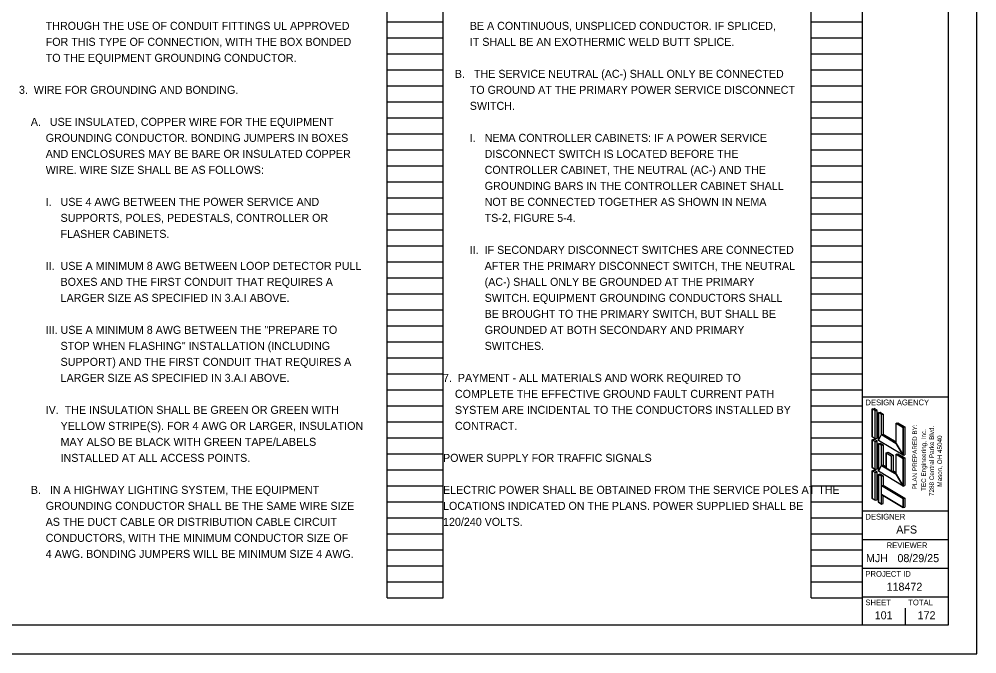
# Model space of a CAD drawing. Extents: x 0 to 34, y 0 to 22.
# Drawn here: x 17.24 to 34, y 0 to 11.11 of the extents above; entities that cross this region are included whole.
import ezdxf

# ---------------------------------------------------------------- set-up
doc = ezdxf.new("R2010")
doc.units = 0
for name, color, linetype in [('Default', 7, 'Continuous'), ('SH_Border', 7, 'Continuous'), ('SH_Cut_Line', 7, 'Continuous'), ('SH_Data', 7, 'Continuous'), ('SH_Text', 7, 'Continuous')]:
    doc.layers.add(name, color=color, linetype=linetype)

msp = doc.modelspace()

# ---------------------------------------------------------------- linework, layer by layer
at = {"layer": 'SH_Border'}
for p, q in [((32, 0.5), (32, 21.5)), ((32, 4.5), (33.5, 4.5)), ((32, 2.5), (33.5, 2.5)), ((32, 2), (33.5, 2)), ((32, 1.5), (33.5, 1.5)), ((32, 1), (33.5, 1))]:
    msp.add_line(p, q, dxfattribs=at)
msp.add_lwpolyline([(1.5, 21.5), (33.5, 21.5), (33.5, 0.5), (1.5, 0.5)], close=True, dxfattribs=at)
at = {"layer": 'SH_Cut_Line'}
msp.add_lwpolyline([(0, 0), (34, 0), (34, 22), (0, 22)], close=True, dxfattribs=at)
at = {"layer": 'SH_Data'}
for p, q in [((23.68, 0.98), (23.68, 21.14)), ((24.66, 0.98), (24.66, 21.14)), ((31.1, 0.98), (31.1, 21.14)), ((32, 0.98), (32, 21.14)), ((23.68, 11.06), (24.66, 11.06)), ((31.1, 11.06), (32, 11.06)), ((23.68, 10.78), (24.66, 10.78)), ((31.1, 10.78), (32, 10.78)), ((23.68, 10.5), (24.66, 10.5)), ((31.1, 10.5), (32, 10.5)), ((23.68, 10.22), (24.66, 10.22)), ((31.1, 10.22), (32, 10.22)), ((23.68, 9.94), (24.66, 9.94)), ((31.1, 9.94), (32, 9.94)), ((23.68, 9.66), (24.66, 9.66)), ((31.1, 9.66), (32, 9.66)), ((23.68, 9.38), (24.66, 9.38)), ((31.1, 9.38), (32, 9.38)), ((23.68, 9.1), (24.66, 9.1)), ((31.1, 9.1), (32, 9.1)), ((23.68, 8.82), (24.66, 8.82)), ((31.1, 8.82), (32, 8.82)), ((23.68, 8.54), (24.66, 8.54)), ((31.1, 8.54), (32, 8.54)), ((23.68, 8.26), (24.66, 8.26)), ((31.1, 8.26), (32, 8.26)), ((23.68, 7.98), (24.66, 7.98)), ((31.1, 7.98), (32, 7.98)), ((23.68, 7.7), (24.66, 7.7)), ((31.1, 7.7), (32, 7.7)), ((23.68, 7.42), (24.66, 7.42)), ((31.1, 7.42), (32, 7.42)), ((23.68, 7.14), (24.66, 7.14)), ((31.1, 7.14), (32, 7.14)), ((23.68, 6.86), (24.66, 6.86)), ((31.1, 6.86), (32, 6.86)), ((23.68, 6.58), (24.66, 6.58)), ((31.1, 6.58), (32, 6.58)), ((23.68, 6.3), (24.66, 6.3)), ((31.1, 6.3), (32, 6.3)), ((23.68, 6.02), (24.66, 6.02)), ((31.1, 6.02), (32, 6.02)), ((23.68, 5.74), (24.66, 5.74)), ((31.1, 5.74), (32, 5.74)), ((23.68, 5.46), (24.66, 5.46)), ((31.1, 5.46), (32, 5.46)), ((23.68, 5.18), (24.66, 5.18)), ((31.1, 5.18), (32, 5.18)), ((23.68, 4.9), (24.66, 4.9)), ((31.1, 4.9), (32, 4.9)), ((23.68, 4.62), (24.66, 4.62)), ((31.1, 4.62), (32, 4.62)), ((23.68, 4.34), (24.66, 4.34)), ((31.1, 4.34), (32, 4.34)), ((23.68, 4.06), (24.66, 4.06)), ((31.1, 4.06), (32, 4.06)), ((23.68, 3.78), (24.66, 3.78)), ((31.1, 3.78), (32, 3.78)), ((23.68, 3.5), (24.66, 3.5)), ((31.1, 3.5), (32, 3.5)), ((32.75, 3.5), (32.75, 3.5)), ((23.68, 3.22), (24.66, 3.22)), ((31.1, 3.22), (32, 3.22)), ((23.68, 2.94), (24.66, 2.94)), ((31.1, 2.94), (32, 2.94)), ((23.68, 2.66), (24.66, 2.66)), ((31.1, 2.66), (32, 2.66)), ((23.68, 2.38), (24.66, 2.38)), ((31.1, 2.38), (32, 2.38)), ((23.68, 2.1), (24.66, 2.1)), ((31.1, 2.1), (32, 2.1)), ((23.68, 1.82), (24.66, 1.82)), ((31.1, 1.82), (32, 1.82)), ((23.68, 1.54), (24.66, 1.54)), ((31.1, 1.54), (32, 1.54)), ((23.68, 1.26), (24.66, 1.26)), ((31.1, 1.26), (32, 1.26)), ((23.68, 0.98), (24.66, 0.98)), ((31.1, 0.98), (32, 0.98)), ((32.375, 0.675), (32.375, 0.675)), ((32.75, 0.5), (32.75, 0.8))]:
    msp.add_line(p, q, dxfattribs=at)
at = {"layer": 'SH_Text'}
for p, q in [((32.169, 4.285), (32.201, 4.294)), ((32.169, 3.799), (32.169, 4.285)), ((32.223, 4.253), (32.169, 4.285)), ((32.255, 4.261), (32.201, 4.294)), ((32.223, 4.253), (32.255, 4.261)), ((32.223, 3.767), (32.223, 4.253)), ((32.255, 3.775), (32.255, 4.261)), ((32.277, 4.221), (32.309, 4.229)), ((32.331, 4.188), (32.277, 4.221)), ((32.277, 3.735), (32.277, 4.221)), ((32.309, 4.229), (32.363, 4.196)), ((32.331, 4.188), (32.363, 4.196)), ((32.363, 4.196), (32.363, 3.845)), ((32.331, 3.837), (32.331, 4.188)), ((32.587, 4.034), (32.62, 4.042)), ((32.587, 3.683), (32.587, 4.034)), ((32.709, 3.961), (32.587, 4.034)), ((32.62, 4.042), (32.741, 3.97)), ((32.709, 3.961), (32.741, 3.97)), ((32.709, 3.475), (32.709, 3.961)), ((32.741, 3.97), (32.741, 3.484)), ((32.223, 3.767), (32.169, 3.799)), ((32.169, 3.745), (32.201, 3.754)), ((32.169, 3.259), (32.169, 3.745)), ((32.223, 3.713), (32.169, 3.745)), ((32.255, 3.722), (32.201, 3.754)), ((32.223, 3.767), (32.255, 3.775)), ((32.223, 3.713), (32.255, 3.722)), ((32.223, 3.227), (32.223, 3.713)), ((32.255, 3.236), (32.255, 3.722)), ((32.709, 3.475), (32.277, 3.735)), ((32.277, 3.681), (32.309, 3.689)), ((32.309, 3.689), (32.363, 3.656)), ((32.331, 3.837), (32.363, 3.845)), ((32.587, 3.683), (32.331, 3.837)), ((32.363, 3.845), (32.587, 3.711)), ((32.277, 3.195), (32.277, 3.681)), ((32.331, 3.648), (32.277, 3.681)), ((32.331, 3.648), (32.363, 3.656)), ((32.331, 3.297), (32.331, 3.648)), ((32.363, 3.656), (32.363, 3.305)), ((32.415, 3.519), (32.448, 3.527)), ((32.415, 3.519), (32.415, 3.247)), ((32.415, 3.519), (32.503, 3.466)), ((32.448, 3.527), (32.535, 3.474)), ((32.503, 3.466), (32.535, 3.474)), ((32.503, 3.466), (32.503, 3.194)), ((32.535, 3.474), (32.535, 3.202)), ((32.587, 3.494), (32.62, 3.502)), ((32.587, 3.143), (32.587, 3.494)), ((32.709, 3.421), (32.587, 3.494)), ((32.62, 3.502), (32.741, 3.43)), ((32.709, 3.475), (32.741, 3.484)), ((32.709, 3.421), (32.741, 3.43)), ((32.709, 2.935), (32.709, 3.421)), ((32.741, 3.43), (32.741, 2.944)), ((32.223, 3.227), (32.169, 3.259)), ((32.169, 3.205), (32.201, 3.215)), ((32.169, 2.719), (32.169, 3.205)), ((32.223, 3.173), (32.169, 3.205)), ((32.255, 3.181), (32.201, 3.215)), ((32.223, 3.227), (32.255, 3.236)), ((32.709, 2.935), (32.277, 3.195)), ((32.331, 3.297), (32.363, 3.305)), ((32.415, 3.247), (32.331, 3.297)), ((32.363, 3.305), (32.415, 3.274)), ((32.503, 3.194), (32.535, 3.202)), ((32.587, 3.143), (32.503, 3.194)), ((32.535, 3.202), (32.587, 3.171)), ((32.222, 3.173), (32.255, 3.181)), ((32.223, 2.687), (32.223, 3.173)), ((32.255, 2.695), (32.255, 3.181)), ((32.277, 3.141), (32.309, 3.151)), ((32.331, 3.108), (32.277, 3.141)), ((32.277, 2.655), (32.277, 3.141)), ((32.309, 3.151), (32.363, 3.116)), ((32.331, 3.108), (32.363, 3.116)), ((32.331, 2.944), (32.331, 3.108)), ((32.363, 3.116), (32.363, 2.952)), ((32.331, 2.944), (32.363, 2.952)), ((32.331, 2.944), (32.709, 2.717)), ((32.363, 2.952), (32.741, 2.725)), ((32.709, 2.935), (32.741, 2.944)), ((32.223, 2.687), (32.169, 2.719)), ((32.223, 2.687), (32.255, 2.695)), ((32.331, 2.787), (32.709, 2.56)), ((32.331, 2.622), (32.331, 2.787)), ((32.363, 2.63), (32.363, 2.767)), ((32.709, 2.717), (32.741, 2.725)), ((32.709, 2.56), (32.709, 2.717)), ((32.741, 2.725), (32.741, 2.568)), ((32.331, 2.622), (32.277, 2.655)), ((32.331, 2.622), (32.363, 2.63)), ((32.709, 2.56), (32.741, 2.568))]:
    msp.add_line(p, q, dxfattribs=at)
for points in [[(32.169, 3.799), (32.223, 3.767), (32.223, 4.253), (32.169, 4.285)], [(32.277, 3.735), (32.331, 3.837), (32.331, 4.188), (32.277, 4.221)], [(32.709, 3.475), (32.587, 3.683), (32.587, 4.034), (32.709, 3.961)], [(32.169, 3.259), (32.223, 3.227), (32.223, 3.713), (32.169, 3.745)], [(32.277, 3.735), (32.331, 3.837), (32.587, 3.683), (32.709, 3.475)], [(32.277, 3.195), (32.331, 3.297), (32.331, 3.648), (32.277, 3.681)], [(32.415, 3.247), (32.415, 3.519), (32.503, 3.466), (32.503, 3.194)], [(32.709, 2.935), (32.587, 3.143), (32.587, 3.494), (32.709, 3.421)], [(32.169, 2.719), (32.223, 2.687), (32.223, 3.173), (32.169, 3.205)], [(32.277, 3.195), (32.331, 3.297), (32.587, 3.143), (32.709, 2.935)], [(32.277, 2.655), (32.331, 2.622), (32.331, 3.108), (32.277, 3.141)], [(32.331, 2.787), (32.331, 2.944), (32.709, 2.717), (32.709, 2.56)]]:
    msp.add_lwpolyline(points, close=True, dxfattribs=at)

# ---------------------------------------------------------------- texts
at = {"layer": 'Default'}
for s, p in [('PLAN PREPARED BY:', (32.954, 2.88)), ('TEC Engineering, Inc.', (33.11, 2.851)), ('7288 Central Parke Blvd.', (33.25, 2.762)), ('Mason, OH 45040', (33.39, 2.925))]:
    msp.add_text(s, height=0.08, rotation=90, dxfattribs=at).set_placement(p)
at = {"layer": 'SH_Data'}
for s, height, p in [('DESIGN AGENCY', 0.1, (32.05, 4.35)), ('DESIGNER', 0.1, (32.05, 2.35)), ('AFS', 0.14, (32.59, 2.105)), ('REVIEWER', 0.1, (32.422, 1.85)), ('MJH', 0.14, (32.061, 1.605)), ('08/29/25', 0.14, (32.611, 1.605)), ('PROJECT ID', 0.1, (32.05, 1.35)), ('118472', 0.14, (32.421, 1.105)), ('SHEET', 0.1, (32.05, 0.85)), ('TOTAL', 0.1, (32.8, 0.85)), ('101', 0.14, (32.213, 0.605)), ('172', 0.14, (32.964, 0.605))]:
    msp.add_text(s, height=height, dxfattribs=at).set_placement(p)
at = {"layer": 'SH_Text'}
for s, p in [('         THROUGH THE USE OF CONDUIT FITTINGS UL APPROVED', (17.24, 10.92)), ('         BE A CONTINUOUS, UNSPLICED CONDUCTOR. IF SPLICED,', (24.66, 10.92)), ('         FOR THIS TYPE OF CONNECTION, WITH THE BOX BONDED', (17.24, 10.64)), ('         IT SHALL BE AN EXOTHERMIC WELD BUTT SPLICE.', (24.66, 10.64)), ('         TO THE EQUIPMENT GROUNDING CONDUCTOR.', (17.24, 10.36)), ('    B.   THE SERVICE NEUTRAL (AC-) SHALL ONLY BE CONNECTED', (24.66, 10.08)), ('3.  WIRE FOR GROUNDING AND BONDING.', (17.24, 9.8)), ('         TO GROUND AT THE PRIMARY POWER SERVICE DISCONNECT', (24.66, 9.8)), ('         SWITCH.', (24.66, 9.52)), ('    A.   USE INSULATED, COPPER WIRE FOR THE EQUIPMENT', (17.24, 9.24)), ('         GROUNDING CONDUCTOR. BONDING JUMPERS IN BOXES', (17.24, 8.96)), ('         I.   NEMA CONTROLLER CABINETS: IF A POWER SERVICE', (24.66, 8.96)), ('         AND ENCLOSURES MAY BE BARE OR INSULATED COPPER', (17.24, 8.68)), ('              DISCONNECT SWITCH IS LOCATED BEFORE THE', (24.66, 8.68)), ('              CONTROLLER CABINET, THE NEUTRAL (AC-) AND THE', (24.66, 8.4)), ('         WIRE. WIRE SIZE SHALL BE AS FOLLOWS:', (17.24, 8.4)), ('              GROUNDING BARS IN THE CONTROLLER CABINET SHALL', (24.66, 8.12)), ('         I.   USE 4 AWG BETWEEN THE POWER SERVICE AND', (17.24, 7.84)), ('              NOT BE CONNECTED TOGETHER AS SHOWN IN NEMA', (24.66, 7.84)), ('              SUPPORTS, POLES, PEDESTALS, CONTROLLER OR', (17.24, 7.56)), ('              TS-2, FIGURE 5-4.', (24.66, 7.56)), ('              FLASHER CABINETS.', (17.24, 7.28)), ('         II.  IF SECONDARY DISCONNECT SWITCHES ARE CONNECTED', (24.66, 7)), ('         II.  USE A MINIMUM 8 AWG BETWEEN LOOP DETECTOR PULL', (17.24, 6.72)), ('              AFTER THE PRIMARY DISCONNECT SWITCH, THE NEUTRAL', (24.66, 6.72)), ('              BOXES AND THE FIRST CONDUIT THAT REQUIRES A', (17.24, 6.44)), ('              (AC-) SHALL ONLY BE GROUNDED AT THE PRIMARY', (24.66, 6.44)), ('              LARGER SIZE AS SPECIFIED IN 3.A.I ABOVE.', (17.24, 6.16)), ('              SWITCH. EQUIPMENT GROUNDING CONDUCTORS SHALL', (24.66, 6.16)), ('              BE BROUGHT TO THE PRIMARY SWITCH, BUT SHALL BE', (24.66, 5.88)), ('         III. USE A MINIMUM 8 AWG BETWEEN THE "PREPARE TO', (17.24, 5.6)), ('              GROUNDED AT BOTH SECONDARY AND PRIMARY', (24.66, 5.6)), ('              STOP WHEN FLASHING" INSTALLATION (INCLUDING', (17.24, 5.32)), ('              SWITCHES.', (24.66, 5.32)), ('              SUPPORT) AND THE FIRST CONDUIT THAT REQUIRES A', (17.24, 5.04)), ('              LARGER SIZE AS SPECIFIED IN 3.A.I ABOVE.', (17.24, 4.76)), ('7.  PAYMENT - ALL MATERIALS AND WORK REQUIRED TO', (24.66, 4.76)), ('    COMPLETE THE EFFECTIVE GROUND FAULT CURRENT PATH', (24.66, 4.48)), ('         IV.  THE INSULATION SHALL BE GREEN OR GREEN WITH', (17.24, 4.2)), ('    SYSTEM ARE INCIDENTAL TO THE CONDUCTORS INSTALLED BY', (24.66, 4.2)), ('              YELLOW STRIPE(S). FOR 4 AWG OR LARGER, INSULATION', (17.24, 3.92)), ('    CONTRACT.', (24.66, 3.92)), ('              MAY ALSO BE BLACK WITH GREEN TAPE/LABELS', (17.24, 3.64)), ('              INSTALLED AT ALL ACCESS POINTS.', (17.24, 3.36)), ('POWER SUPPLY FOR TRAFFIC SIGNALS', (24.66, 3.36)), ('    B.   IN A HIGHWAY LIGHTING SYSTEM, THE EQUIPMENT', (17.24, 2.8)), ('ELECTRIC POWER SHALL BE OBTAINED FROM THE SERVICE POLES AT THE ', (24.66, 2.8)), ('         GROUNDING CONDUCTOR SHALL BE THE SAME WIRE SIZE', (17.24, 2.52)), ('LOCATIONS INDICATED ON THE PLANS. POWER SUPPLIED SHALL BE ', (24.66, 2.52)), ('         AS THE DUCT CABLE OR DISTRIBUTION CABLE CIRCUIT', (17.24, 2.24)), ('120/240 VOLTS.', (24.66, 2.24)), ('         CONDUCTORS, WITH THE MINIMUM CONDUCTOR SIZE OF', (17.24, 1.96)), ('         4 AWG. BONDING JUMPERS WILL BE MINIMUM SIZE 4 AWG.', (17.24, 1.68))]:
    msp.add_text(s, height=0.14, dxfattribs=at).set_placement(p)

doc.saveas('drawing.dxf')
